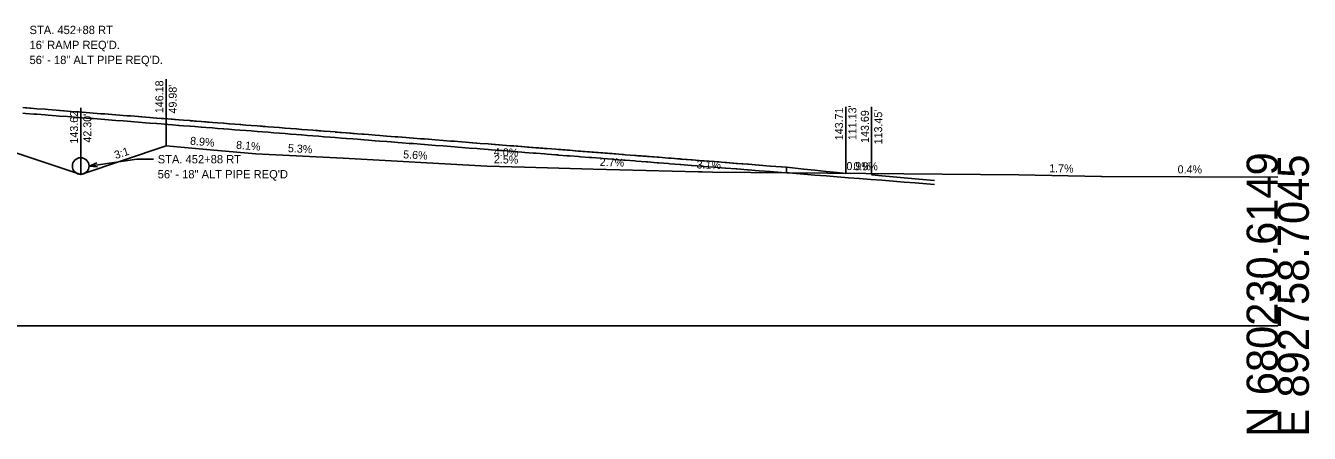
# Model space of a CAD drawing. Extents: x -26 to 4403, y -13 to 9578.
# Drawn here: x 287.4 to 402.8, y 1490.3 to 1527 of the extents above; entities that cross this region are included whole.
import ezdxf

# ---------------------------------------------------------------- set-up
doc = ezdxf.new("R2010")
doc.units = 0
for name, color, linetype in [('CONST_DCH', 7, 'Continuous'), ('CONST_LV3', 7, 'Continuous'), ('DTM_CORRIDOR', 7, 'Continuous'), ('DTM_P_FINISHED_GRADE', 7, 'Continuous'), ('DTM_X_GROUND', 7, 'Continuous'), ('X_PROFILES_1', 7, 'Continuous'), ('XS_CELL', 7, 'Continuous'), ('XS_P_DR_GRAVEL', 7, 'Continuous'), ('XS_P_DRAINAGE', 7, 'Continuous'), ('XS_P_GROUND', 7, 'Continuous'), ('XS_P_TX_CLEARZONE', 7, 'Continuous'), ('XS_P_TX_FS_BS', 7, 'Continuous')]:
    doc.layers.add(name, color=color, linetype=linetype)

msp = doc.modelspace()

# ---------------------------------------------------------------- linework, layer by layer
at = {"layer": 'CONST_LV3'}
msp.add_lwpolyline([(287.09, 1519.63), (287.83, 1519.57), (288.09, 1519.55), (288.36, 1519.53), (289.1, 1519.48), (289.37, 1519.45), (290.1, 1519.4), (290.81, 1519.34), (291.1, 1519.32), (291.8, 1519.26), (292.11, 1519.24), (292.8, 1519.19), (293.11, 1519.16), (293.79, 1519.11), (294.11, 1519.08), (294.78, 1519.03), (295.12, 1519.01), (295.46, 1518.98), (296.12, 1518.93), (296.77, 1518.88), (297.13, 1518.85), (297.76, 1518.8), (298.13, 1518.77), (298.51, 1518.74), (299.13, 1518.69), (299.75, 1518.64), (300.14, 1518.61), (300.74, 1518.57), (301.14, 1518.53), (301.55, 1518.5), (302.15, 1518.46), (302.73, 1518.41), (303.15, 1518.38), (303.72, 1518.33), (304.15, 1518.3), (304.6, 1518.26), (305.16, 1518.22), (305.7, 1518.18), (306.16, 1518.14), (306.7, 1518.1), (307.16, 1518.06), (307.64, 1518.03), (308.17, 1517.98), (308.68, 1517.94), (309.17, 1517.91), (309.68, 1517.87), (310.18, 1517.83), (310.67, 1517.79), (311.18, 1517.75), (311.66, 1517.71), (312.18, 1517.67), (312.72, 1517.63), (313.19, 1517.59), (313.65, 1517.56), (314.19, 1517.51), (314.75, 1517.47), (315.19, 1517.44), (315.63, 1517.4), (316.2, 1517.36), (316.63, 1517.32), (317.2, 1517.28), (317.62, 1517.25), (318.21, 1517.2), (318.81, 1517.15), (319.21, 1517.12), (319.82, 1517.07), (320.21, 1517.04), (320.6, 1517.01), (321.22, 1516.96), (321.59, 1516.93), (322.22, 1516.89), (322.58, 1516.86), (323.23, 1516.81), (323.58, 1516.78), (324.23, 1516.73), (324.9, 1516.68), (325.23, 1516.65), (325.56, 1516.62), (326.24, 1516.57), (326.56, 1516.55), (327.24, 1516.49), (327.55, 1516.47), (328.24, 1516.41), (328.95, 1516.36), (329.25, 1516.34), (329.54, 1516.31), (330.25, 1516.26), (330.98, 1516.2), (331.26, 1516.18), (331.52, 1516.16), (332.26, 1516.1), (332.51, 1516.08), (333.26, 1516.02), (333.51, 1516), (334.27, 1515.94), (335.04, 1515.88), (335.27, 1515.87), (335.49, 1515.85), (336.28, 1515.79), (337.07, 1515.72), (337.28, 1515.71), (337.48, 1515.69), (338.28, 1515.63), (338.47, 1515.61), (339.29, 1515.55), (339.46, 1515.54), (340.29, 1515.47), (340.46, 1515.46), (341.29, 1515.39), (342.15, 1515.33), (342.3, 1515.32), (342.44, 1515.3), (343.3, 1515.24), (343.44, 1515.23), (344.31, 1515.16), (345.19, 1515.09), (345.31, 1515.08), (345.42, 1515.07), (346.31, 1515), (346.42, 1514.99), (347.32, 1514.92), (348.24, 1514.85), (348.32, 1514.84), (348.4, 1514.84), (349.32, 1514.77), (350.27, 1514.69), (350.33, 1514.69), (350.39, 1514.68), (351.33, 1514.61), (351.38, 1514.61), (352.34, 1514.53), (352.37, 1514.53), (353.34, 1514.45), (354.33, 1514.37), (354.34, 1514.37), (354.36, 1514.37), (355.35, 1514.3), (355.35, 1514.29), (355.79, 1514.26)], dxfattribs=at)
at = {"layer": 'DTM_P_FINISHED_GRADE'}
msp.add_lwpolyline([(287.1, 1519.63), (287.35, 1519.61), (288.09, 1519.55), (288.1, 1519.55), (288.37, 1519.53), (289.1, 1519.48), (289.11, 1519.48), (289.38, 1519.45), (290.1, 1519.4), (290.11, 1519.4), (290.4, 1519.37), (291.1, 1519.32), (291.11, 1519.32), (291.41, 1519.29), (292.11, 1519.24), (292.12, 1519.24), (292.43, 1519.22), (293.11, 1519.16), (293.12, 1519.16), (293.44, 1519.14), (294.11, 1519.08), (294.12, 1519.08), (294.46, 1519.06), (295.12, 1519.01), (295.13, 1519), (295.47, 1518.98), (296.12, 1518.93), (296.13, 1518.93), (296.49, 1518.9), (297.13, 1518.85), (297.14, 1518.85), (297.5, 1518.82), (298.13, 1518.77), (298.14, 1518.77), (298.52, 1518.74), (299.13, 1518.69), (299.14, 1518.69), (299.53, 1518.66), (300.14, 1518.61), (300.15, 1518.61), (300.55, 1518.58), (301.14, 1518.53), (301.15, 1518.53), (301.56, 1518.5), (302.15, 1518.46), (302.15, 1518.45), (302.58, 1518.42), (303.15, 1518.38), (303.16, 1518.38), (303.59, 1518.34), (304.15, 1518.3), (304.16, 1518.3), (304.61, 1518.26), (305.16, 1518.22), (305.17, 1518.22), (305.62, 1518.18), (306.16, 1518.14), (306.17, 1518.14), (306.63, 1518.1), (307.16, 1518.06), (307.17, 1518.06), (307.65, 1518.03), (308.17, 1517.98), (308.18, 1517.98), (308.66, 1517.95), (309.17, 1517.91), (309.18, 1517.91), (309.68, 1517.87), (310.18, 1517.83), (310.18, 1517.83), (310.69, 1517.79), (311.18, 1517.75), (311.19, 1517.75), (311.71, 1517.71), (312.18, 1517.67), (312.19, 1517.67), (312.72, 1517.63), (313.19, 1517.59), (313.19, 1517.59), (313.74, 1517.55), (314.19, 1517.51), (314.2, 1517.51), (314.75, 1517.47), (315.19, 1517.44), (315.2, 1517.43), (315.77, 1517.39), (316.2, 1517.36), (316.21, 1517.36), (316.78, 1517.31), (317.2, 1517.28), (317.21, 1517.28), (317.8, 1517.23), (318.21, 1517.2), (318.21, 1517.2), (318.81, 1517.15), (319.21, 1517.12), (319.22, 1517.12), (319.83, 1517.07), (320.21, 1517.04), (320.22, 1517.04), (320.84, 1516.99), (321.22, 1516.96), (321.22, 1516.96), (321.86, 1516.91), (322.22, 1516.89), (322.23, 1516.89), (322.87, 1516.83), (323.23, 1516.81), (323.23, 1516.81), (323.89, 1516.76), (324.23, 1516.73), (324.23, 1516.73), (324.9, 1516.68), (325.23, 1516.65), (325.24, 1516.65), (325.92, 1516.6), (326.24, 1516.57), (326.24, 1516.57), (326.93, 1516.52), (327.24, 1516.49), (327.25, 1516.49), (327.94, 1516.44), (328.24, 1516.41), (328.25, 1516.41), (328.96, 1516.36), (329.25, 1516.34), (329.25, 1516.34), (329.97, 1516.28), (330.25, 1516.26), (330.26, 1516.26), (330.99, 1516.2), (331.26, 1516.18), (331.26, 1516.18), (332, 1516.12), (332.26, 1516.1), (332.26, 1516.1), (333.02, 1516.04), (333.26, 1516.02), (333.27, 1516.02), (334.03, 1515.96), (334.27, 1515.94), (334.27, 1515.94), (335.05, 1515.88), (335.27, 1515.87), (335.27, 1515.86), (336.06, 1515.8), (336.28, 1515.79), (336.28, 1515.79), (337.08, 1515.72), (337.28, 1515.71), (337.28, 1515.71), (338.09, 1515.64), (338.28, 1515.63), (338.29, 1515.63), (339.11, 1515.57), (339.29, 1515.55), (339.29, 1515.55), (340.12, 1515.49), (340.29, 1515.47), (340.29, 1515.47), (341.14, 1515.41), (341.29, 1515.39), (341.3, 1515.39), (342.15, 1515.33), (342.3, 1515.32), (342.3, 1515.32), (343.17, 1515.25), (343.3, 1515.24), (343.3, 1515.24), (344.18, 1515.17), (344.31, 1515.16), (344.31, 1515.16), (345.2, 1515.09), (345.31, 1515.08), (345.31, 1515.08), (346.21, 1515.01), (346.31, 1515), (346.31, 1515), (347.22, 1514.93), (347.32, 1514.92), (347.32, 1514.92), (348.24, 1514.85), (348.32, 1514.84), (348.32, 1514.84), (349.25, 1514.77), (349.32, 1514.77), (349.33, 1514.77), (350.27, 1514.69), (350.33, 1514.69), (350.33, 1514.69), (351.28, 1514.61), (351.33, 1514.61), (351.33, 1514.61), (352.3, 1514.53), (352.34, 1514.53), (352.34, 1514.53), (353.31, 1514.45), (353.34, 1514.45), (353.34, 1514.45), (354.33, 1514.37), (354.34, 1514.37), (354.34, 1514.37), (355.34, 1514.3), (355.35, 1514.3), (355.35, 1514.3), (355.79, 1514.26)], dxfattribs=at)
at = {"layer": 'DTM_X_GROUND'}
msp.add_lwpolyline([(299.98, 1516.19), (303.96, 1515.84), (306.35, 1515.62), (308.07, 1515.48), (315.91, 1515.07), (328.84, 1514.35), (332.23, 1514.26), (338.41, 1514.09), (347.87, 1513.84), (348.21, 1513.84), (349.14, 1513.81), (376.69, 1513.57), (384.12, 1513.44), (384.18, 1513.43), (400, 1513.37)], dxfattribs=at)
at = {"layer": 'XS_CELL'}
msp.add_line((250, 1500), (400, 1500), dxfattribs=at)
at = {"layer": 'XS_P_DR_GRAVEL'}
for points in [[(287.1, 1519.13), (287.35, 1519.11), (288.09, 1519.05), (288.1, 1519.05), (288.37, 1519.03), (289.1, 1518.98), (289.11, 1518.98), (289.38, 1518.95), (290.1, 1518.9), (290.11, 1518.9), (290.4, 1518.87), (291.1, 1518.82), (291.11, 1518.82), (291.41, 1518.79), (292.11, 1518.74), (292.12, 1518.74), (292.43, 1518.72), (293.11, 1518.66), (293.12, 1518.66), (293.44, 1518.64), (294.11, 1518.58), (294.12, 1518.58), (294.46, 1518.56), (295.12, 1518.51), (295.13, 1518.5), (295.47, 1518.48), (296.12, 1518.43), (296.13, 1518.43), (296.49, 1518.4), (297.13, 1518.35), (297.14, 1518.35), (297.5, 1518.32), (298.13, 1518.27), (298.14, 1518.27), (298.52, 1518.24), (299.13, 1518.19), (299.14, 1518.19), (299.53, 1518.16), (300.14, 1518.11), (300.15, 1518.11), (300.55, 1518.08), (301.14, 1518.03), (301.15, 1518.03), (301.56, 1518), (302.15, 1517.96), (302.15, 1517.95), (302.58, 1517.92), (303.15, 1517.88), (303.16, 1517.88), (303.59, 1517.84), (304.15, 1517.8), (304.16, 1517.8), (304.61, 1517.76), (305.16, 1517.72), (305.17, 1517.72), (305.62, 1517.68), (306.16, 1517.64), (306.17, 1517.64), (306.63, 1517.6), (307.16, 1517.56), (307.17, 1517.56), (307.65, 1517.53), (308.17, 1517.48), (308.18, 1517.48), (308.66, 1517.45), (309.17, 1517.41), (309.18, 1517.41), (309.68, 1517.37), (310.18, 1517.33), (310.18, 1517.33), (310.69, 1517.29), (311.18, 1517.25), (311.19, 1517.25), (311.71, 1517.21), (312.18, 1517.17), (312.19, 1517.17), (312.72, 1517.13), (313.19, 1517.09), (313.19, 1517.09), (313.74, 1517.05), (314.19, 1517.01), (314.2, 1517.01), (314.75, 1516.97), (315.19, 1516.94), (315.2, 1516.93), (315.77, 1516.89), (316.2, 1516.86), (316.21, 1516.86), (316.78, 1516.81), (317.2, 1516.78), (317.21, 1516.78), (317.8, 1516.73), (318.21, 1516.7), (318.21, 1516.7), (318.81, 1516.65), (319.21, 1516.62), (319.22, 1516.62), (319.83, 1516.57), (320.21, 1516.54), (320.22, 1516.54), (320.84, 1516.49), (321.22, 1516.46), (321.22, 1516.46), (321.86, 1516.41), (322.22, 1516.39), (322.23, 1516.39), (322.87, 1516.33), (323.23, 1516.31), (323.23, 1516.31), (323.89, 1516.26), (324.23, 1516.23), (324.23, 1516.23), (324.9, 1516.18), (325.23, 1516.15), (325.24, 1516.15), (325.92, 1516.1), (326.24, 1516.07), (326.24, 1516.07), (326.93, 1516.02), (327.24, 1515.99), (327.25, 1515.99), (327.94, 1515.94), (328.24, 1515.91), (328.25, 1515.91), (328.96, 1515.86), (329.25, 1515.84), (329.25, 1515.84), (329.97, 1515.78), (330.25, 1515.76), (330.26, 1515.76), (330.99, 1515.7), (331.26, 1515.68), (331.26, 1515.68), (332, 1515.62), (332.26, 1515.6), (332.26, 1515.6), (333.02, 1515.54), (333.26, 1515.52), (333.27, 1515.52), (334.03, 1515.46), (334.27, 1515.44), (334.27, 1515.44), (335.05, 1515.38), (335.27, 1515.37), (335.27, 1515.36), (336.06, 1515.3), (336.28, 1515.29), (336.28, 1515.29), (337.08, 1515.22), (337.28, 1515.21), (337.28, 1515.21), (338.09, 1515.14), (338.28, 1515.13), (338.29, 1515.13), (339.11, 1515.07), (339.29, 1515.05), (339.29, 1515.05), (340.12, 1514.99), (340.29, 1514.97), (340.29, 1514.97), (341.14, 1514.91), (341.29, 1514.89), (341.3, 1514.89), (342.15, 1514.83), (342.3, 1514.82), (342.3, 1514.82), (343.17, 1514.75), (343.3, 1514.74), (343.3, 1514.74), (344.18, 1514.67), (344.31, 1514.66), (344.31, 1514.66), (345.2, 1514.59), (345.31, 1514.58), (345.31, 1514.58), (346.21, 1514.51), (346.31, 1514.5), (346.31, 1514.5), (347.22, 1514.43), (347.32, 1514.42), (347.32, 1514.42), (348.24, 1514.35), (348.32, 1514.34), (348.32, 1514.34), (349.25, 1514.27), (349.32, 1514.27), (349.33, 1514.27), (350.27, 1514.19), (350.33, 1514.19), (350.33, 1514.19), (351.28, 1514.11), (351.33, 1514.11), (351.33, 1514.11), (352.3, 1514.03), (352.34, 1514.03), (352.34, 1514.03), (353.31, 1513.95), (353.34, 1513.95), (353.34, 1513.95), (354.33, 1513.87), (354.34, 1513.87), (354.34, 1513.87), (355.34, 1513.8), (355.35, 1513.8), (355.35, 1513.8), (355.79, 1513.76), (355.79, 1514.26), (355.35, 1514.3), (355.35, 1514.3), (355.34, 1514.3), (354.34, 1514.37), (354.34, 1514.37), (354.33, 1514.37), (353.34, 1514.45), (353.34, 1514.45), (353.31, 1514.45), (352.34, 1514.53), (352.34, 1514.53), (352.3, 1514.53), (351.33, 1514.61), (351.33, 1514.61), (351.28, 1514.61), (350.33, 1514.69), (350.33, 1514.69), (350.27, 1514.69), (349.33, 1514.77), (349.32, 1514.77), (349.25, 1514.77), (348.32, 1514.84), (348.32, 1514.84), (348.24, 1514.85), (347.32, 1514.92), (347.32, 1514.92), (347.22, 1514.93), (346.31, 1515), (346.31, 1515), (346.21, 1515.01), (345.31, 1515.08), (345.31, 1515.08), (345.2, 1515.09), (344.31, 1515.16), (344.31, 1515.16), (344.18, 1515.17), (343.3, 1515.24), (343.3, 1515.24), (343.17, 1515.25), (342.3, 1515.32), (342.3, 1515.32), (342.15, 1515.33), (341.3, 1515.39), (341.29, 1515.39), (341.14, 1515.41), (340.29, 1515.47), (340.29, 1515.47), (340.12, 1515.49), (339.29, 1515.55), (339.29, 1515.55), (339.11, 1515.57), (338.29, 1515.63), (338.28, 1515.63), (338.09, 1515.64), (337.28, 1515.71), (337.28, 1515.71), (337.08, 1515.72), (336.28, 1515.79), (336.28, 1515.79), (336.06, 1515.8), (335.27, 1515.86), (335.27, 1515.87), (335.05, 1515.88), (334.27, 1515.94), (334.27, 1515.94), (334.03, 1515.96), (333.27, 1516.02), (333.26, 1516.02), (333.02, 1516.04), (332.26, 1516.1), (332.26, 1516.1), (332, 1516.12), (331.26, 1516.18), (331.26, 1516.18), (330.99, 1516.2), (330.26, 1516.26), (330.25, 1516.26), (329.97, 1516.28), (329.25, 1516.34), (329.25, 1516.34), (328.96, 1516.36), (328.25, 1516.41), (328.24, 1516.41), (327.94, 1516.44), (327.25, 1516.49), (327.24, 1516.49), (326.93, 1516.52), (326.24, 1516.57), (326.24, 1516.57), (325.92, 1516.6), (325.24, 1516.65), (325.23, 1516.65), (324.9, 1516.68), (324.23, 1516.73), (324.23, 1516.73), (323.89, 1516.76), (323.23, 1516.81), (323.23, 1516.81), (322.87, 1516.83), (322.23, 1516.89), (322.22, 1516.89), (321.86, 1516.91), (321.22, 1516.96), (321.22, 1516.96), (320.84, 1516.99), (320.22, 1517.04), (320.21, 1517.04), (319.83, 1517.07), (319.22, 1517.12), (319.21, 1517.12), (318.81, 1517.15), (318.21, 1517.2), (318.21, 1517.2), (317.8, 1517.23), (317.21, 1517.28), (317.2, 1517.28), (316.78, 1517.31), (316.21, 1517.36), (316.2, 1517.36), (315.77, 1517.39), (315.2, 1517.43), (315.19, 1517.44), (314.75, 1517.47), (314.2, 1517.51), (314.19, 1517.51), (313.74, 1517.55), (313.19, 1517.59), (313.19, 1517.59), (312.72, 1517.63), (312.19, 1517.67), (312.18, 1517.67), (311.71, 1517.71), (311.19, 1517.75), (311.18, 1517.75), (310.69, 1517.79), (310.18, 1517.83), (310.18, 1517.83), (309.68, 1517.87), (309.18, 1517.91), (309.17, 1517.91), (308.66, 1517.95), (308.18, 1517.98), (308.17, 1517.98), (307.65, 1518.03), (307.17, 1518.06), (307.16, 1518.06), (306.63, 1518.1), (306.17, 1518.14), (306.16, 1518.14), (305.62, 1518.18), (305.17, 1518.22), (305.16, 1518.22), (304.61, 1518.26), (304.16, 1518.3), (304.15, 1518.3), (303.59, 1518.34), (303.16, 1518.38), (303.15, 1518.38), (302.58, 1518.42), (302.15, 1518.45), (302.15, 1518.46), (301.56, 1518.5), (301.15, 1518.53), (301.14, 1518.53), (300.55, 1518.58), (300.15, 1518.61), (300.14, 1518.61), (299.53, 1518.66), (299.14, 1518.69), (299.13, 1518.69), (298.52, 1518.74), (298.14, 1518.77), (298.13, 1518.77), (297.5, 1518.82), (297.14, 1518.85), (297.13, 1518.85), (296.49, 1518.9), (296.13, 1518.93), (296.12, 1518.93), (295.47, 1518.98), (295.13, 1519), (295.12, 1519.01), (294.46, 1519.06), (294.12, 1519.08), (294.11, 1519.08), (293.44, 1519.14), (293.12, 1519.16), (293.11, 1519.16), (292.43, 1519.22), (292.12, 1519.24), (292.11, 1519.24), (291.41, 1519.29), (291.11, 1519.32), (291.1, 1519.32), (290.4, 1519.37), (290.11, 1519.4), (290.1, 1519.4), (289.38, 1519.45), (289.11, 1519.48), (289.1, 1519.48), (288.37, 1519.53), (288.1, 1519.55), (288.09, 1519.55), (287.35, 1519.61), (287.1, 1519.63)], [(355.79, 1513.76), (356.35, 1513.72), (357.36, 1513.64), (358.36, 1513.56), (359.36, 1513.48), (360.37, 1513.4), (361.37, 1513.32), (362.37, 1513.25), (363.38, 1513.17), (364.38, 1513.09), (365.39, 1513.01), (366.39, 1512.93), (367.39, 1512.85), (368.4, 1512.77), (369.13, 1512.72)]]:
    msp.add_lwpolyline(points, dxfattribs=at)
at = {"layer": 'XS_P_DRAINAGE'}
for p in [(293.05, 1514.37), (298.85, 1514.98)]:
    msp.add_line(p, (297.35, 1514.98), dxfattribs=at)
msp.add_lwpolyline([(293.82, 1514.29), (293.05, 1514.37), (293.76, 1514.66)], dxfattribs=at)
msp.add_circle((292.3, 1514.37), 0.75, dxfattribs=at)
at = {"layer": 'XS_P_GROUND'}
for points in [[(292.3, 1513.62), (289.25, 1514.64), (280, 1517.72), (270.97, 1519.98), (268, 1520.72)], [(292.3, 1513.62), (299.98, 1516.18)], [(355.79, 1514.26), (356.35, 1514.2), (357.36, 1514.1), (358.36, 1513.99), (359.36, 1513.89), (360.37, 1513.79), (361.13, 1513.71)], [(364.38, 1513.49), (363.48, 1513.57), (363.45, 1513.69)], [(364.38, 1513.49), (365.39, 1513.4), (366.39, 1513.31), (367.39, 1513.22), (368.4, 1513.14), (369.13, 1513.07)]]:
    msp.add_lwpolyline(points, dxfattribs=at)
at = {"layer": 'XS_P_TX_CLEARZONE'}
for p, q in [((299.98, 1516.18), (299.98, 1522.18)), ((292.3, 1513.62), (292.3, 1519.62)), ((361.13, 1513.71), (361.13, 1519.71)), ((363.45, 1513.69), (363.45, 1519.69))]:
    msp.add_line(p, q, dxfattribs=at)

# ---------------------------------------------------------------- texts
at = {"layer": 'CONST_DCH'}
msp.add_text('X', height=0.12, dxfattribs=at).set_placement((292.26, 1513.56))
at = {"layer": 'DTM_CORRIDOR'}
msp.add_text('X', height=0.12, dxfattribs=at).set_placement((299.94, 1516.12))
at = {"layer": 'X_PROFILES_1'}
for p in [(361.09, 1513.65), (363.41, 1513.63)]:
    msp.add_text('X', height=0.12, dxfattribs=at).set_placement(p)
at = {"layer": 'XS_CELL'}
for s, p in [('N 680230.6149', (400, 1490)), ('E 892758.7045', (402.8, 1490))]:
    msp.add_text(s, height=2.8, rotation=90, dxfattribs=at).set_placement(p)
at = {"layer": 'XS_P_DRAINAGE'}
for s, p in [('STA. 452+88 RT', (287.7, 1526.25)), ("16' RAMP REQ'D.", (287.7, 1524.9)), ('56\' - 18" ALT PIPE REQ\'D.', (287.7, 1523.55)), ('STA. 452+88 RT', (299.23, 1514.61)), ('56\' - 18" ALT PIPE REQ\'D', (299.23, 1513.26))]:
    msp.add_text(s, height=0.75, dxfattribs=at).set_placement(p)
at = {"layer": 'XS_P_TX_CLEARZONE'}
for s, p in [('146.18', (299.74, 1519.13)), ("49.98'", (300.94, 1519.1)), ('143.62', (292.06, 1516.39)), ("42.30'", (293.26, 1516.48)), ('143.71', (360.89, 1516.69)), ("111.13'", (362.09, 1516.7)), ('143.69', (363.21, 1516.45)), ("113.45'", (364.41, 1516.32))]:
    msp.add_text(s, height=0.72, rotation=90, dxfattribs=at).set_placement(p)
at = {"layer": 'XS_P_TX_FS_BS'}
for s, rotation, p in [('8.9%', 354.899, (302.12, 1516.3)), ('8.9%', 354.899, (302.12, 1516.3)), ('8.1%', 355.3462, (306.26, 1515.93)), ('8.1%', 355.3462, (306.26, 1515.93)), ('3:1', 18.4349, (295.46, 1514.99)), ('5.3%', 356.9863, (310.93, 1515.63)), ('5.3%', 356.9863, (310.93, 1515.63)), ('5.6%', 356.805, (321.3, 1515.07)), ('5.6%', 356.805, (321.3, 1515.07)), ('4.0%', 357.6852, (329.46, 1515.29)), ('2.5%', 358.5457, (329.47, 1514.63)), ('2.5%', 358.5457, (329.47, 1514.63)), ('2.7%', 358.4536, (338.99, 1514.38)), ('2.7%', 358.4536, (338.99, 1514.38)), ('3.1%', 358.2017, (347.7, 1514.16)), ('3.1%', 358.2017, (347.7, 1514.16)), ('0.9%', 359.4933, (361.19, 1514.01)), ('0.9%', 359.4933, (361.82, 1514)), ('0.9%', 359.4933, (361.82, 1514)), ('1.7%', 359.0411, (379.43, 1513.82)), ('1.7%', 359.0411, (379.43, 1513.82)), ('0.4%', 359.7826, (390.99, 1513.71)), ('0.4%', 359.7826, (390.99, 1513.71))]:
    msp.add_text(s, height=0.72, rotation=rotation, dxfattribs=at).set_placement(p)

doc.saveas('drawing.dxf')
